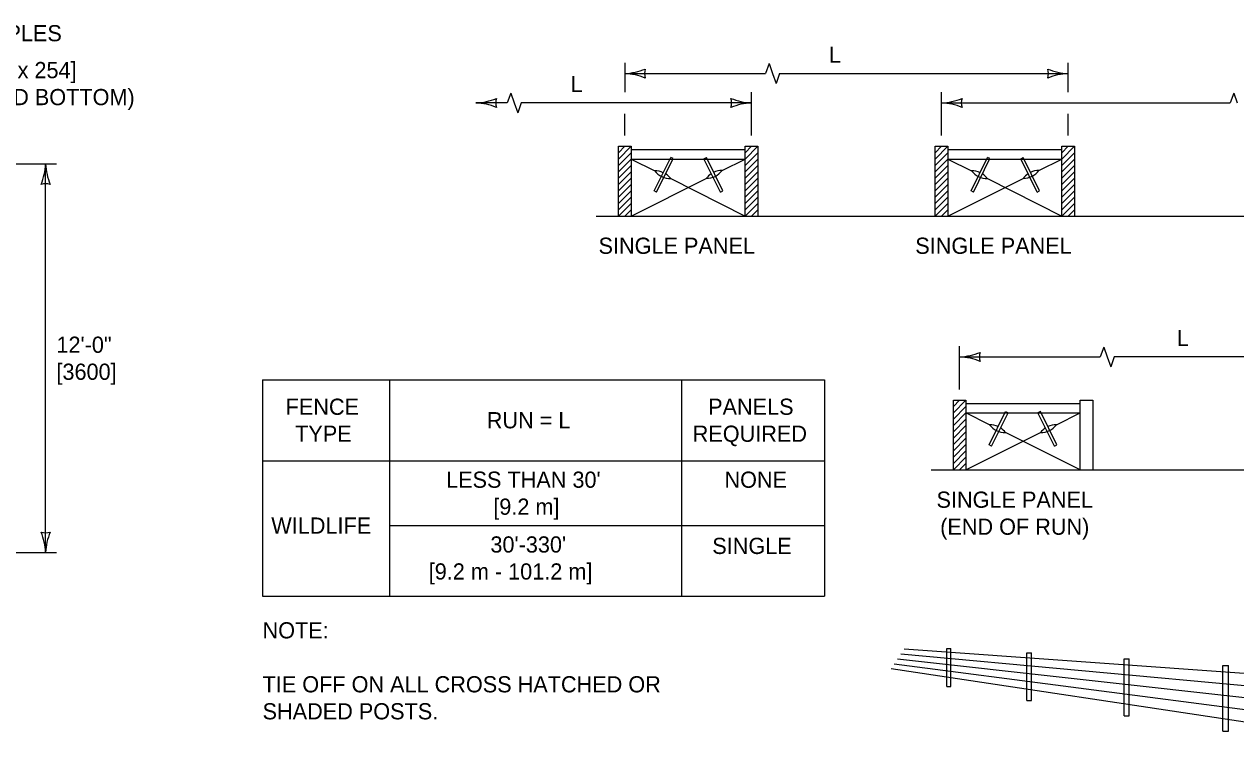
# Model space of a CAD drawing. Extents: x 49991.4 to 50021, y 49987.6 to 50011.4.
# Drawn here: x 50005.896 to 50010.385, y 49992.222 to 49994.895 of the extents above; entities that cross this region are included whole.
import ezdxf

# ---------------------------------------------------------------- set-up
doc = ezdxf.new("R2010")
doc.units = 0
for name, color, linetype in [('Level 1', 7, 'Continuous'), ('Level 2', 7, 'Continuous'), ('Level 3', 7, 'Continuous')]:
    doc.layers.add(name, color=color, linetype=linetype)

msp = doc.modelspace()

# ---------------------------------------------------------------- linework, layer by layer
at = {"layer": 'Level 1'}
for p, q in [((50008.0979, 49994.1848), (50008.0979, 49994.4431)), ((50008.0979, 49994.4431), (50008.1449, 49994.4431)), ((50008.0979, 49994.3961), (50008.1449, 49994.4431)), ((50008.0979, 49994.4195), (50008.1214, 49994.4431)), ((50008.1449, 49994.4431), (50008.1449, 49994.1848)), ((50008.5675, 49994.1848), (50008.5675, 49994.4431)), ((50008.5675, 49994.4431), (50008.6144, 49994.4431)), ((50008.5675, 49994.3961), (50008.6144, 49994.4431)), ((50008.5675, 49994.4195), (50008.5909, 49994.4431)), ((50008.6144, 49994.4431), (50008.6144, 49994.1848)), ((50009.2718, 49994.1848), (50009.2718, 49994.4431)), ((50009.2718, 49994.4431), (50009.3188, 49994.4431)), ((50009.2718, 49994.3961), (50009.3188, 49994.4431)), ((50009.2718, 49994.4195), (50009.2952, 49994.4431)), ((50009.3188, 49994.4431), (50009.3188, 49994.1848)), ((50009.7413, 49994.1848), (50009.7413, 49994.4431)), ((50009.7413, 49994.4431), (50009.7883, 49994.4431)), ((50009.7413, 49994.3961), (50009.7883, 49994.4431)), ((50009.7413, 49994.4195), (50009.7648, 49994.4431)), ((50009.7883, 49994.4431), (50009.7883, 49994.1848)), ((50008.0979, 49994.3726), (50008.1449, 49994.4195)), ((50008.1449, 49994.4313), (50008.5675, 49994.4313)), ((50008.2308, 49994.2776), (50008.2916, 49994.402)), ((50008.3007, 49994.3974), (50008.2916, 49994.402)), ((50008.4145, 49994.3973), (50008.4237, 49994.4019)), ((50008.4842, 49994.2776), (50008.4237, 49994.4019)), ((50008.5675, 49994.3726), (50008.6144, 49994.4195)), ((50009.2718, 49994.3726), (50009.3188, 49994.4195)), ((50009.3188, 49994.4313), (50009.7413, 49994.4313)), ((50009.4048, 49994.2776), (50009.4654, 49994.402)), ((50009.4744, 49994.3974), (50009.4654, 49994.402)), ((50009.5884, 49994.3972), (50009.5976, 49994.4018)), ((50009.6581, 49994.2776), (50009.5976, 49994.4018)), ((50009.7413, 49994.3726), (50009.7883, 49994.4195)), ((50008.0979, 49994.3491), (50008.1449, 49994.3961)), ((50008.0979, 49994.3257), (50008.1449, 49994.3726)), ((50008.1449, 49994.3961), (50008.5675, 49994.3961)), ((50008.1449, 49994.3961), (50008.2324, 49994.3523)), ((50008.2395, 49994.2731), (50008.3007, 49994.3974)), ((50008.4756, 49994.2732), (50008.4145, 49994.3973)), ((50008.4822, 49994.3534), (50008.5675, 49994.3961)), ((50008.5675, 49994.3491), (50008.6144, 49994.3961)), ((50008.5675, 49994.3257), (50008.6144, 49994.3726)), ((50009.2718, 49994.3491), (50009.3188, 49994.3961)), ((50009.2718, 49994.3257), (50009.3188, 49994.3726)), ((50009.3188, 49994.3961), (50009.7413, 49994.3961)), ((50009.3188, 49994.3961), (50009.4063, 49994.3523)), ((50009.4134, 49994.2732), (50009.4746, 49994.3974)), ((50009.6495, 49994.2732), (50009.5884, 49994.3972)), ((50009.656, 49994.3534), (50009.7413, 49994.3961)), ((50009.7413, 49994.3491), (50009.7883, 49994.3961)), ((50009.7413, 49994.3257), (50009.7883, 49994.3726)), ((50008.0979, 49994.3021), (50008.1449, 49994.3491)), ((50008.0979, 49994.2787), (50008.1449, 49994.3257)), ((50008.1449, 49994.1848), (50008.4234, 49994.3244)), ((50008.2917, 49994.3233), (50008.5675, 49994.1848)), ((50008.5675, 49994.3021), (50008.6144, 49994.3491)), ((50008.5675, 49994.2787), (50008.6144, 49994.3257)), ((50009.2718, 49994.3021), (50009.3188, 49994.3491)), ((50009.2718, 49994.2787), (50009.3188, 49994.3257)), ((50009.3188, 49994.1848), (50009.5976, 49994.3244)), ((50009.4652, 49994.3233), (50009.7413, 49994.1848)), ((50009.7413, 49994.3021), (50009.7883, 49994.3491)), ((50009.7413, 49994.2787), (50009.7883, 49994.3257)), ((50008.0979, 49994.2553), (50008.1449, 49994.3021)), ((50008.0979, 49994.2317), (50008.1449, 49994.2787)), ((50008.2395, 49994.2731), (50008.2308, 49994.2776)), ((50008.4756, 49994.2732), (50008.4842, 49994.2776)), ((50008.5675, 49994.2553), (50008.6144, 49994.3021)), ((50008.5675, 49994.2317), (50008.6144, 49994.2787)), ((50009.2718, 49994.2553), (50009.3188, 49994.3021)), ((50009.2718, 49994.2317), (50009.3188, 49994.2787)), ((50009.4134, 49994.2732), (50009.4048, 49994.2776)), ((50009.6495, 49994.2732), (50009.6581, 49994.2776)), ((50009.7413, 49994.2553), (50009.7883, 49994.3021)), ((50009.7413, 49994.2317), (50009.7883, 49994.2787)), ((50008.0979, 49994.2083), (50008.1449, 49994.2553)), ((50008.0979, 49994.1848), (50008.1449, 49994.2317)), ((50008.5675, 49994.2083), (50008.6144, 49994.2553)), ((50008.5675, 49994.1848), (50008.6144, 49994.2317)), ((50009.2718, 49994.2083), (50009.3188, 49994.2553)), ((50009.2718, 49994.1848), (50009.3188, 49994.2317)), ((50009.7413, 49994.2083), (50009.7883, 49994.2553)), ((50009.7413, 49994.1848), (50009.7883, 49994.2317)), ((50008.0157, 49994.1848), (50011.0438, 49994.1848)), ((50008.1214, 49994.1848), (50008.1449, 49994.2083)), ((50008.5909, 49994.1848), (50008.6144, 49994.2083)), ((50009.2952, 49994.1848), (50009.3188, 49994.2083)), ((50009.7648, 49994.1848), (50009.7883, 49994.2083)), ((50009.3388, 49993.2439), (50009.3388, 49993.5021)), ((50009.3388, 49993.5021), (50009.3857, 49993.5021)), ((50009.3388, 49993.4552), (50009.3857, 49993.5021)), ((50009.3388, 49993.4786), (50009.3622, 49993.5021)), ((50009.3857, 49993.5021), (50009.3857, 49993.2439)), ((50009.8082, 49993.2439), (50009.8082, 49993.5021)), ((50009.8082, 49993.5021), (50009.8551, 49993.5021)), ((50009.8551, 49993.5021), (50009.8551, 49993.2439)), ((50009.3388, 49993.4317), (50009.3857, 49993.4786)), ((50009.3857, 49993.4904), (50009.8082, 49993.4904)), ((50009.4716, 49993.3366), (50009.5323, 49993.461)), ((50009.4802, 49993.3322), (50009.5415, 49993.4563)), ((50009.5323, 49993.461), (50009.5415, 49993.4563)), ((50009.6616, 49993.461), (50009.6524, 49993.4563)), ((50009.7137, 49993.3322), (50009.6524, 49993.4563)), ((50009.7223, 49993.3366), (50009.6616, 49993.461)), ((50009.3388, 49993.4082), (50009.3857, 49993.4552)), ((50009.3388, 49993.3848), (50009.3857, 49993.4317)), ((50009.3857, 49993.4552), (50009.8082, 49993.4552)), ((50009.4733, 49993.4114), (50009.3857, 49993.4552)), ((50009.7206, 49993.4114), (50009.8082, 49993.4552)), ((50009.3388, 49993.3613), (50009.3857, 49993.4082)), ((50009.3388, 49993.3378), (50009.3857, 49993.3848)), ((50009.3857, 49993.2439), (50009.6618, 49993.3824)), ((50009.8082, 49993.2439), (50009.5321, 49993.3824)), ((50009.3388, 49993.3144), (50009.3857, 49993.3613)), ((50009.3388, 49993.2909), (50009.3857, 49993.3378)), ((50009.4802, 49993.3322), (50009.4716, 49993.3366)), ((50009.7137, 49993.3322), (50009.7223, 49993.3366)), ((50009.3388, 49993.2674), (50009.3857, 49993.3144)), ((50009.3388, 49993.2439), (50009.3857, 49993.2909)), ((50009.2569, 49993.2439), (50012.7785, 49993.2439)), ((50009.3622, 49993.2439), (50009.3857, 49993.2674)), ((50011.0069, 49992.3908), (50009.144, 49992.5611)), ((50011.0049, 49992.4472), (50009.1565, 49992.5802)), ((50009.315, 49992.583), (50009.3293, 49992.583)), ((50009.315, 49992.442), (50009.315, 49992.583)), ((50009.3293, 49992.442), (50009.3293, 49992.583)), ((50009.6116, 49992.5664), (50009.6282, 49992.5664)), ((50009.6116, 49992.3902), (50009.6116, 49992.5664)), ((50009.6282, 49992.3902), (50009.6282, 49992.5664)), ((50011.0061, 49992.2782), (50009.1199, 49992.5244)), ((50011.0057, 49992.3347), (50009.1319, 49992.5427)), ((50009.9712, 49992.5441), (50009.9901, 49992.5441)), ((50009.9712, 49992.3328), (50009.9712, 49992.5441)), ((50009.9901, 49992.3328), (50009.9901, 49992.5441)), ((50010.337, 49992.52), (50010.3589, 49992.52)), ((50010.337, 49992.2759), (50010.337, 49992.52)), ((50010.3589, 49992.2759), (50010.3589, 49992.52)), ((50011.0061, 49992.2222), (50009.1083, 49992.5067)), ((50009.315, 49992.442), (50009.3293, 49992.442)), ((50009.6116, 49992.3902), (50009.6282, 49992.3902)), ((50009.9712, 49992.3328), (50009.9901, 49992.3328)), ((50010.337, 49992.2759), (50010.3589, 49992.2759))]:
    msp.add_line(p, q, dxfattribs=at)
for centre, start, end in [((50008.4241, 49994.3972), 269.4411, 323.0376), ((50008.4815, 49994.2806), 89.4411, 115.1092), ((50009.5979, 49994.3972), 269.8075, 323.0285), ((50009.6553, 49994.2806), 89.4411, 115.0236), ((50008.2906, 49994.3961), 216.9715, 270.8412), ((50008.2331, 49994.2795), 64.9162, 90.5589), ((50008.2333, 49994.2798), 36.7006, 57.0535), ((50008.4815, 49994.2806), 123.0147, 143.0285), ((50009.4645, 49994.3961), 216.9715, 270.5589), ((50009.407, 49994.2795), 64.9213, 90.5589), ((50009.407, 49994.2795), 36.9715, 57.0584), ((50009.6555, 49994.2802), 122.913, 142.6032), ((50009.5314, 49993.4552), 216.9715, 270.5589), ((50009.474, 49993.3386), 64.982, 90.5589), ((50009.6625, 49993.4552), 269.4411, 323.0285), ((50009.7199, 49993.3386), 89.4411, 115.018), ((50009.474, 49993.3386), 36.9715, 57.0655), ((50009.7199, 49993.3386), 122.9345, 143.0285)]:
    msp.add_arc(centre, 0.0728, start, end, dxfattribs=at)
at = {"layer": 'Level 2'}
for p, q in [((50006.7793, 49993.5781), (50008.8614, 49993.5781)), ((50006.7794, 49993.5781), (50006.7794, 49992.7769)), ((50007.2501, 49993.5781), (50007.2501, 49992.7769)), ((50008.3312, 49993.5781), (50008.3312, 49992.7769)), ((50008.8614, 49993.5781), (50008.8614, 49992.7769)), ((50006.7793, 49993.2781), (50008.8614, 49993.2781)), ((50007.2501, 49993.038), (50008.8614, 49993.038)), ((50006.7794, 49992.7769), (50008.8614, 49992.7769))]:
    msp.add_line(p, q, dxfattribs=at)
at = {"layer": 'Level 3'}
for p, q in [((50008.1213, 49994.7527), (50008.1213, 49994.6439)), ((50008.1213, 49994.7128), (50008.6431, 49994.7128)), ((50008.6561, 49994.7494), (50008.6431, 49994.7128)), ((50008.6561, 49994.7494), (50008.669, 49994.7128)), ((50008.669, 49994.7128), (50008.682, 49994.6763)), ((50008.695, 49994.7128), (50008.682, 49994.6763)), ((50008.695, 49994.7128), (50009.7645, 49994.7128)), ((50009.7645, 49994.6439), (50009.7645, 49994.7527)), ((50007.6989, 49994.6405), (50007.686, 49994.6039)), ((50007.6989, 49994.6405), (50007.7119, 49994.6039)), ((50008.5908, 49994.4831), (50008.5908, 49994.644)), ((50009.295, 49994.4831), (50009.295, 49994.644)), ((50010.3775, 49994.6405), (50010.3645, 49994.6039)), ((50010.3775, 49994.6405), (50010.3904, 49994.6039)), ((50007.686, 49994.6039), (50007.5698, 49994.6039)), ((50007.7119, 49994.6039), (50007.7248, 49994.5673)), ((50007.7378, 49994.6039), (50007.7248, 49994.5673)), ((50008.5908, 49994.6039), (50007.7378, 49994.6039)), ((50009.295, 49994.6039), (50010.3645, 49994.6039)), ((50008.1214, 49994.4831), (50008.1214, 49994.5639)), ((50009.7645, 49994.4831), (50009.7645, 49994.5639)), ((50005.4534, 49994.378), (50006.0156, 49994.378)), ((50005.9757, 49992.9379), (50005.9757, 49994.378)), ((50009.3622, 49993.5421), (50009.3622, 49993.703)), ((50009.896, 49993.6996), (50009.883, 49993.663)), ((50009.896, 49993.6996), (50009.9089, 49993.663)), ((50009.3622, 49993.663), (50009.883, 49993.663)), ((50009.9089, 49993.663), (50009.9219, 49993.6265)), ((50009.9348, 49993.663), (50009.9219, 49993.6265)), ((50011.0056, 49993.663), (50009.9348, 49993.663)), ((50005.4534, 49992.938), (50006.0156, 49992.938))]:
    msp.add_line(p, q, dxfattribs=at)
for centre, radius, start, end in [((50008.1098, 49994.9455), 0.233, 272.8273, 292.0772), ((50008.1122, 49994.4906), 0.2223, 67.456, 87.6395), ((50008.2496, 49994.7128), 0.0548, 162.1388, 197.8612), ((50009.7736, 49994.9349), 0.2223, 247.456, 267.6395), ((50009.6362, 49994.7128), 0.0548, 342.1388, 17.8612), ((50009.776, 49994.4801), 0.233, 92.8273, 112.0772), ((50007.5583, 49994.8366), 0.233, 272.8273, 292.0772), ((50007.5606, 49994.3818), 0.2223, 67.456, 87.6395), ((50007.698, 49994.6039), 0.0548, 162.1388, 197.8612), ((50008.6, 49994.8261), 0.2223, 247.456, 267.6395), ((50008.4626, 49994.6039), 0.0548, 342.1388, 17.8612), ((50008.6023, 49994.3712), 0.233, 92.8273, 112.0772), ((50009.2835, 49994.8366), 0.233, 272.8273, 292.0772), ((50009.2858, 49994.3818), 0.2223, 67.456, 87.6395), ((50009.4232, 49994.6039), 0.0548, 162.1388, 197.8612), ((50005.7535, 49994.3872), 0.2223, 337.456, 357.6395), ((50006.2084, 49994.3895), 0.233, 182.8273, 202.0772), ((50005.9757, 49994.2498), 0.0548, 72.1388, 107.8612), ((50009.3507, 49993.8957), 0.233, 272.8273, 292.0772), ((50009.4904, 49993.663), 0.0548, 162.1388, 197.8612), ((50009.3531, 49993.4408), 0.2223, 67.456, 87.6395), ((50005.9757, 49993.0661), 0.0548, 252.1388, 287.8612), ((50005.743, 49992.9264), 0.233, 2.8273, 22.0772), ((50006.1978, 49992.9288), 0.2223, 157.456, 177.6395)]:
    msp.add_arc(centre, radius, start, end, dxfattribs=at)

# ---------------------------------------------------------------- texts
at = {"layer": 'Level 2'}
for s, height, p in [('6" [152] HOOKS WITH STAPLES', 0.060003, (50004.839, 49994.8323)), ('L', 0.06, (50008.8781, 49994.7528)), ('[22 DIA. x 254] ', 0.060003, (50005.5596, 49994.6956)), ('L', 0.06, (50007.9209, 49994.644)), ('BOLT HOOK (TYP. TOP AND BOTTOM)', 0.060003, (50004.839, 49994.5956)), ('SINGLE PANEL', 0.06, (50008.0242, 49994.0448)), ('SINGLE PANEL', 0.06, (50009.1978, 49994.0448)), ('12\'-0"', 0.06, (50006.0157, 49993.678)), ('L', 0.06, (50010.1669, 49993.703)), ('[3600]', 0.06, (50006.0157, 49993.578)), ('FENCE', 0.06, (50006.865, 49993.4483)), ('PANELS', 0.06, (50008.4302, 49993.4483)), ('RUN = L', 0.06, (50007.6102, 49993.3983)), ('TYPE', 0.06, (50006.9, 49993.3483)), ('REQUIRED', 0.06, (50008.3731, 49993.3483)), ("LESS THAN 30'", 0.060003, (50007.4593, 49993.178)), ('NONE', 0.06, (50008.4908, 49993.178)), ('[9.2 m]', 0.06, (50007.6343, 49993.078)), ('SINGLE PANEL', 0.06, (50009.2765, 49993.1039)), ('WILDLIFE', 0.06, (50006.8118, 49993.008)), ('(END OF RUN)', 0.06, (50009.29, 49993.0039)), ("30'-330'", 0.06, (50007.6236, 49992.938)), ('SINGLE', 0.06, (50008.4457, 49992.9327)), ('[9.2 m - 101.2 m]', 0.060003, (50007.395, 49992.838)), ('NOTE:', 0.06, (50006.7794, 49992.6199)), ('TIE OFF ON ALL CROSS HATCHED OR', 0.06, (50006.7794, 49992.4199)), ('SHADED POSTS. ', 0.06, (50006.7794, 49992.3199))]:
    msp.add_text(s, height=height, dxfattribs=at).set_placement(p)

doc.saveas('drawing.dxf')
